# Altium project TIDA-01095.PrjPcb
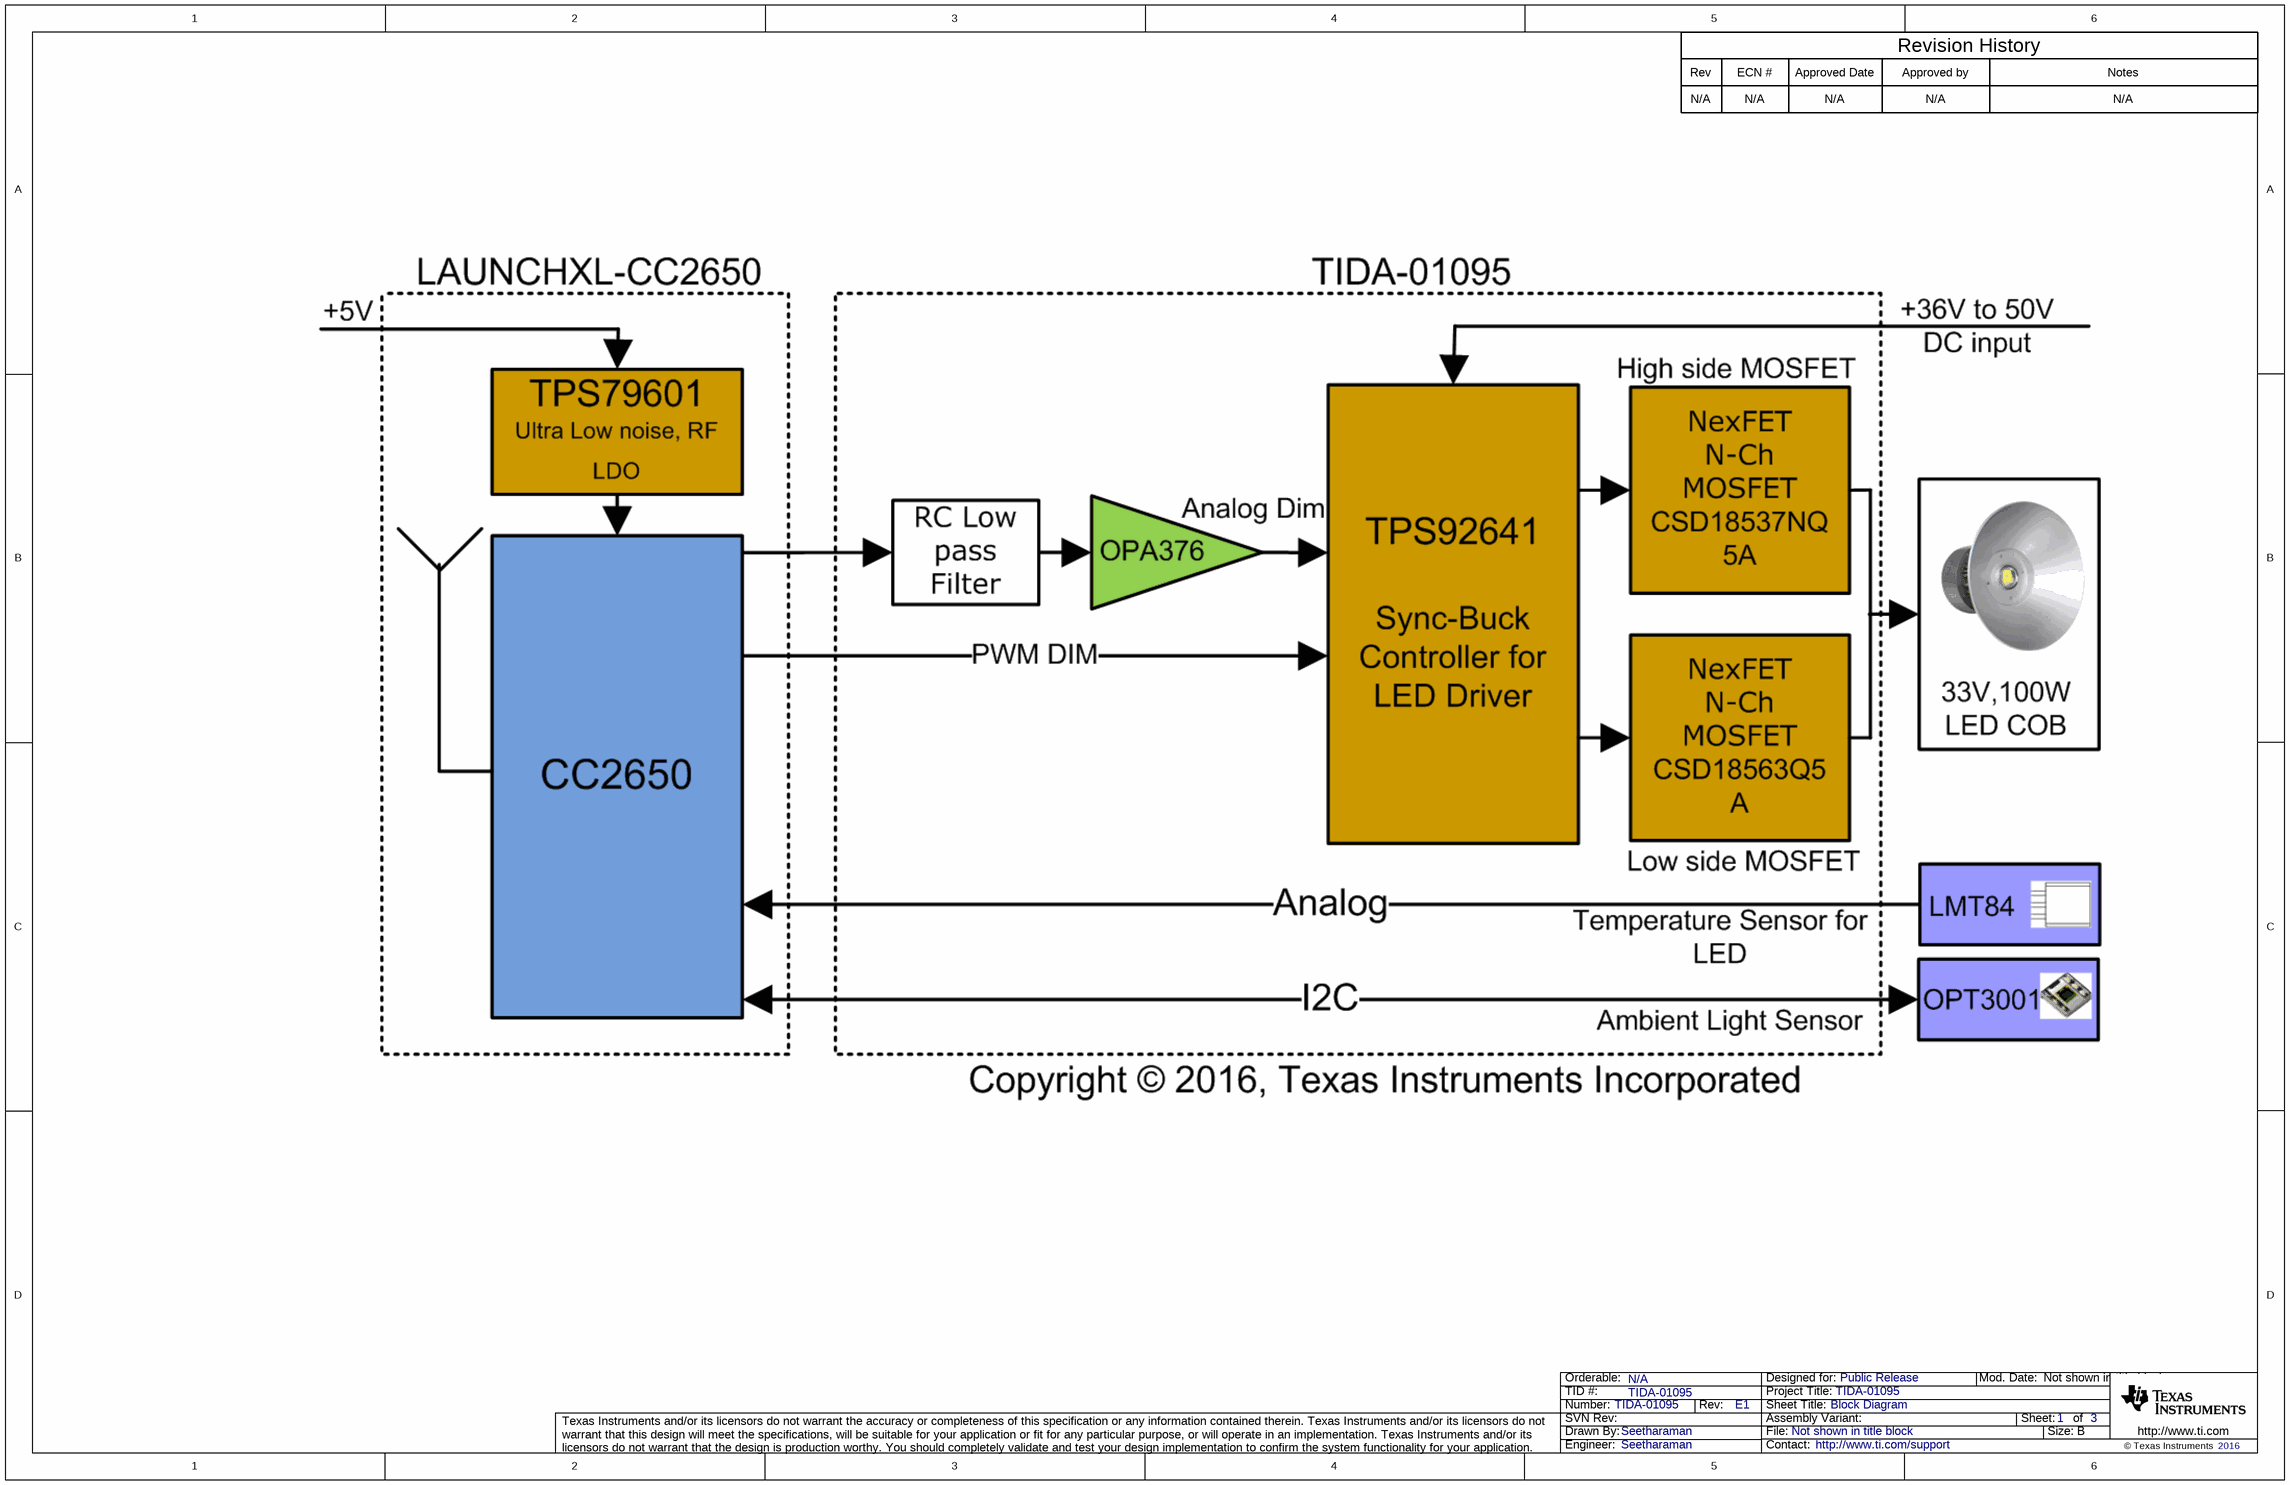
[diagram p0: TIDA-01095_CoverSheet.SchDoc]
CopyrightYear: 2016; EVM_Orderable: N/A; PCB_Layout: Avinash; PCB_Rev: E1; PRJ_Customer: Public Release; PRJ_Engineer: Seetharaman; PRJ_Number: TIDA-01095; PRJ_Title: TIDA-01095; SCH_Rev: E1; TechSupport: http://www.ti.com/support; TID: TIDA-01095
3 sheets, 80 parts. Net scope: global (net labels, ports and power ports of the same name join across sheets).
Board file: TIDA-01095.PcbDoc
Sheets:
  TIDA-01095_CoverSheet.SchDoc
  TIDA-01095_Sheet1.SchDoc
  TIDA-01095_Hardware.SchDoc

## Sheet TIDA-01095_CoverSheet.SchDoc: Block Diagram
size 431 x 279 mm; Date: Not shown in title block; ApprovedBy: Not shown in title block; CheckedBy: Not shown in title block; Author: Not shown in title block; CompanyName: Not shown in title block; DrawnBy: Seetharaman; Engineer: Not shown in title block; Organization: Not shown in title block; Address1: Not shown in title block; Address2: Not shown in title block; Address3: Not shown in title block; Address4: Not shown in title block; DocumentNumber: 1; Revision: Use project parameter SCH_Rev; SheetNumber: 1; SheetTotal: 3; PageSetup: Record=PageOptions¦CenterHorizontal=True¦CenterVertical=True¦PrintScale=1.00¦XCorrection=1.00¦YCorrection=1.00¦PrintKind=0¦BorderSize=5000000¦LeftOffset=0¦BottomOffset=0¦Orientation=2¦PaperLength=1000¦PaperWidth=1000¦Scale=100¦PaperSource=15¦PrintQuality=600¦MediaType=1¦DitherType=10¦PaperKind=Letter¦PrintScaleMode=1

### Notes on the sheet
- Rev
- N/A
- ECN #
- Approved Date
- Approved by
- Revision History
- Notes

## Sheet TIDA-01095_Sheet1.SchDoc: TIDA-01095
size 431 x 279 mm; Date: Not shown in title block; ApprovedBy: Not shown in title block; CheckedBy: Not shown in title block; Author: Not shown in title block; CompanyName: Not shown in title block; DrawnBy: Seetharaman; Engineer: Not shown in title block; Organization: Not shown in title block; Address1: Not shown in title block; Address2: Not shown in title block; Address3: Not shown in title block; Address4: Not shown in title block; DocumentNumber: 1; Revision: Use project parameter SCH_Rev; SheetNumber: 2; SheetTotal: 3; PageSetup: Record=PageOptions¦CenterHorizontal=True¦CenterVertical=True¦PrintScale=1.00¦XCorrection=1.00¦YCorrection=1.00¦PrintKind=0¦BorderSize=5000000¦LeftOffset=0¦BottomOffset=0¦Orientation=2¦PaperLength=1000¦PaperWidth=1000¦Scale=100¦PaperSource=15¦PrintQuality=600¦MediaType=1¦DitherType=10¦PaperKind=Letter¦PrintScaleMode=1
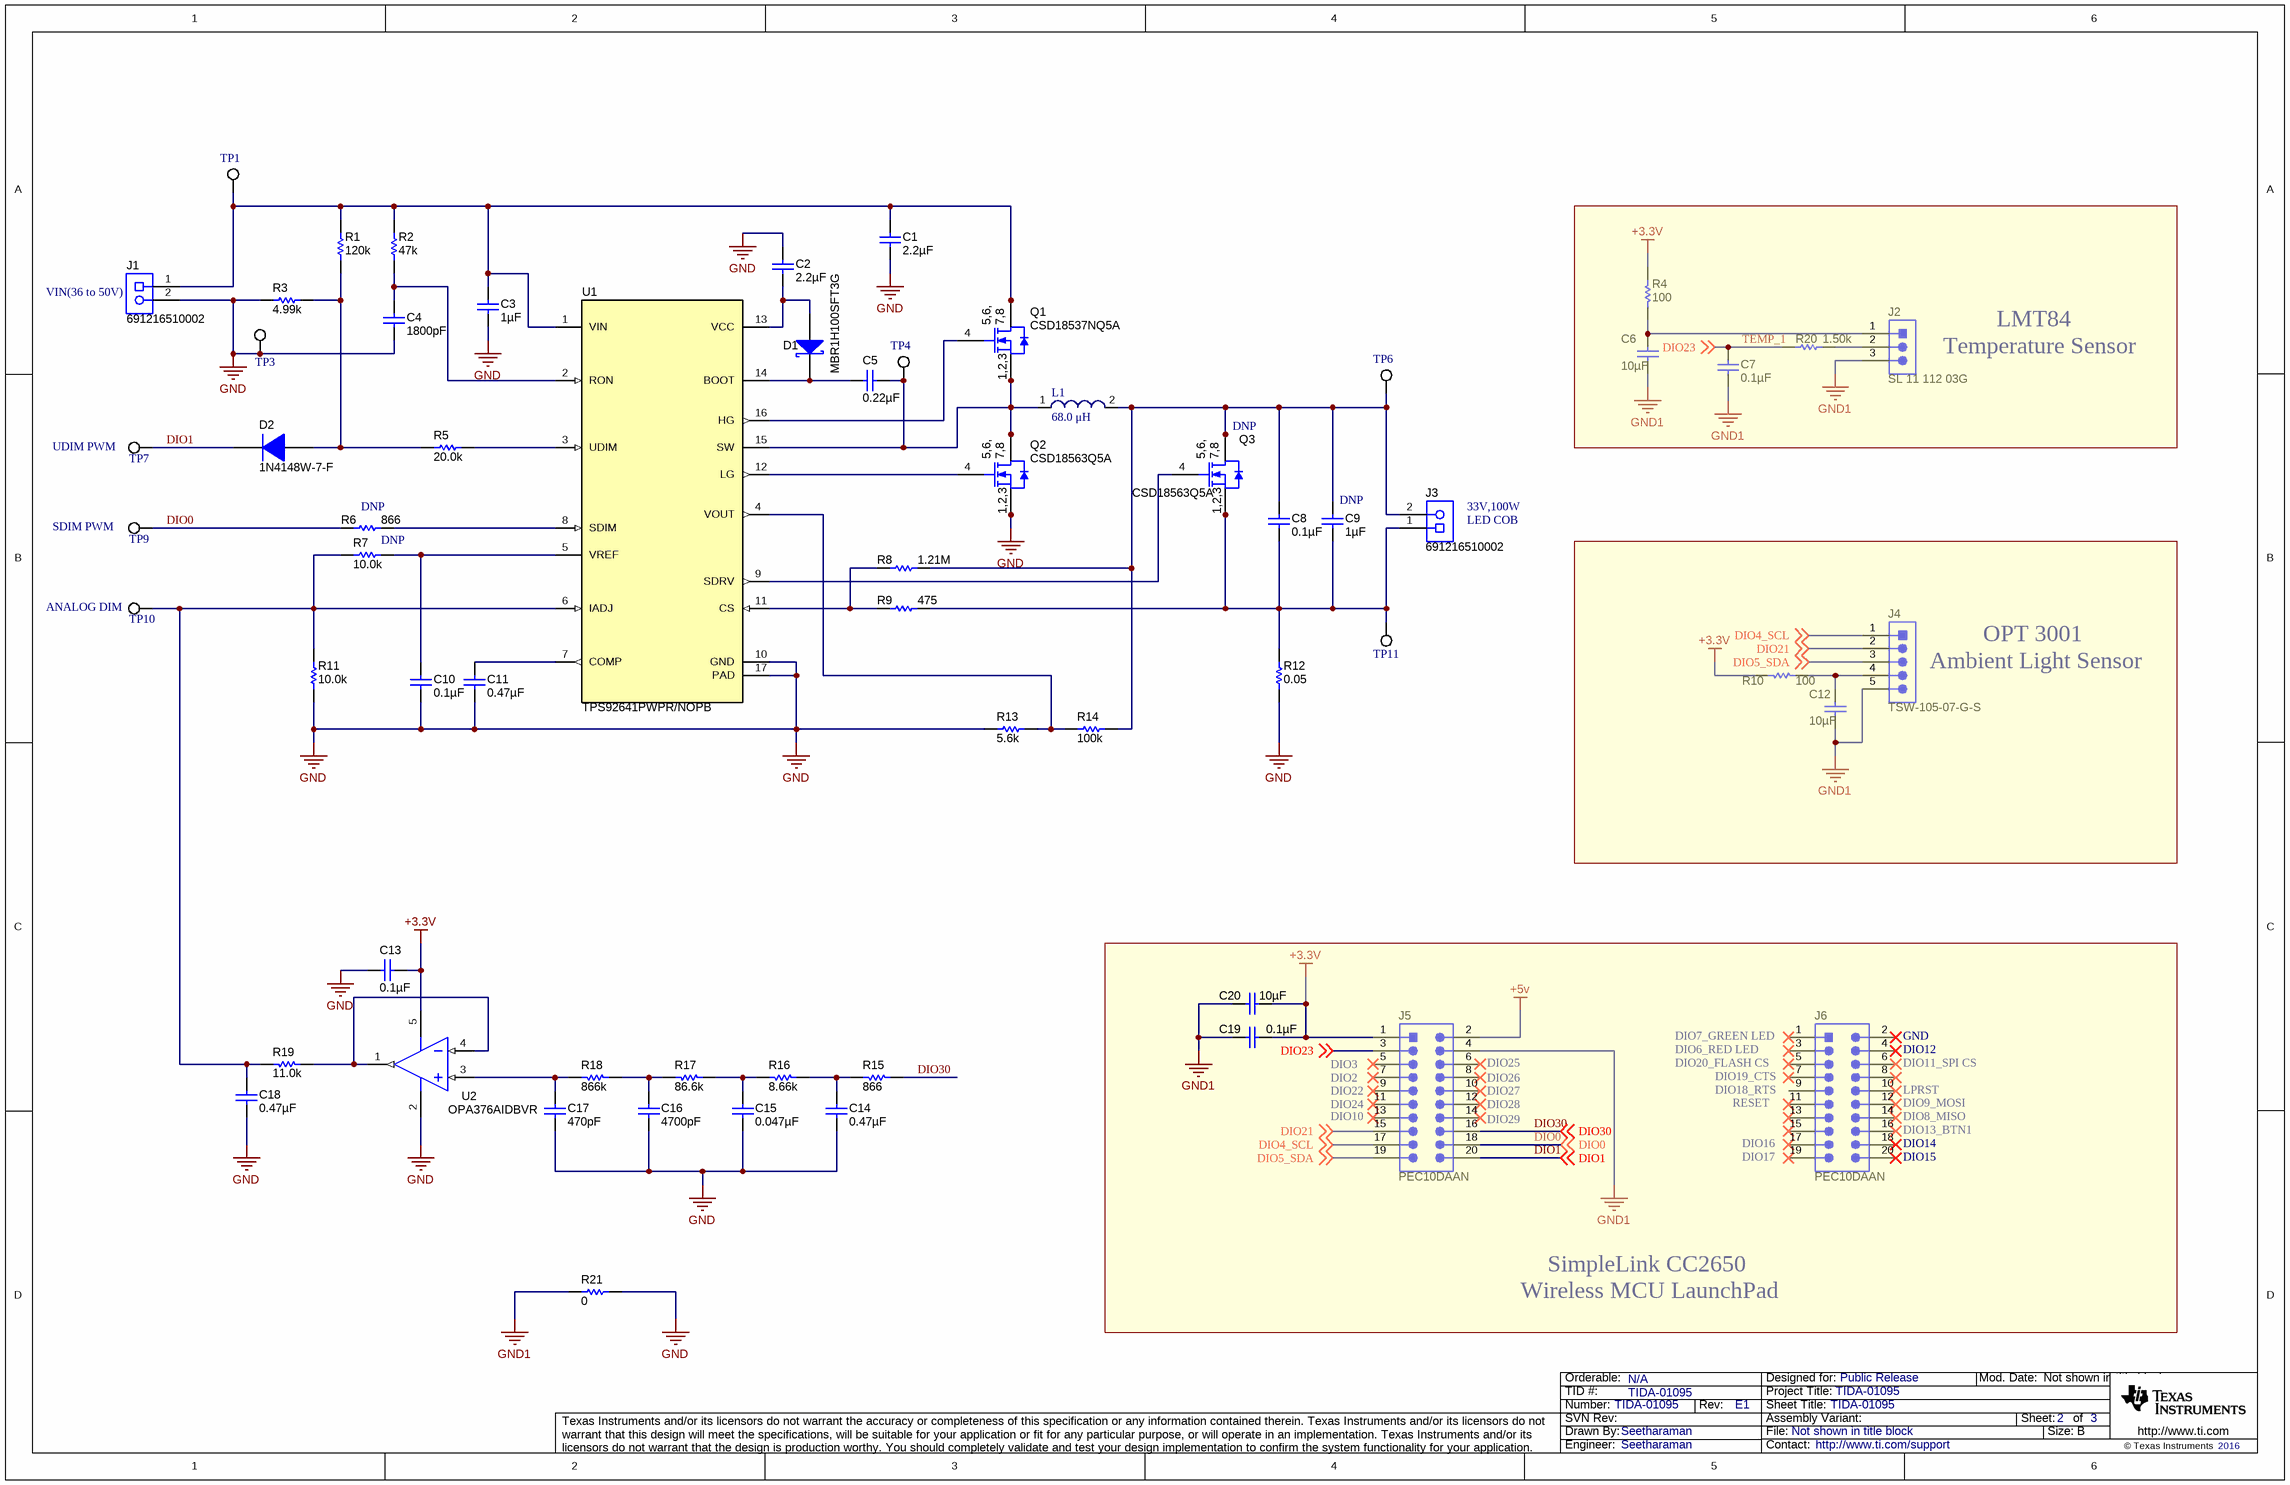
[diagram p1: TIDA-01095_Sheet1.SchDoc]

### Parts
C1  ValueDisplayed: 2.2µF  [1210_270]  (hidden comment: GRM32ER72A225KA35L)
C2  ValueDisplayed: 2.2µF  [0603]  (hidden comment: GRM188R61C225KE15D)
C3  ValueDisplayed: 1µF  [1210]  (hidden comment: C3225X7R2A105K200AA)
C4  ValueDisplayed: 1800pF  [0603]  (hidden comment: GRM188R71E182KA01D)
C5  ValueDisplayed: 0.22µF  [0603]  (hidden comment: GRM188R71E224KA88D)
C6  ValueDisplayed: 10µF  [0603]  (hidden comment: GRT188C81A106ME13D)
C7  ValueDisplayed: 0.1µF  [0603]  (hidden comment: GRM188R71E104KA01D)
C8  ValueDisplayed: 0.1µF  [0603]  (hidden comment: GRM188R71E104KA01D)
C9  ValueDisplayed: 1µF  [1210_200]  (hidden comment: GRM32RR71H105KA01L)
C10  ValueDisplayed: 0.1µF  [0603]  (hidden comment: GRM188R71E104KA01D)
C11  ValueDisplayed: 0.47µF  [0603]  (hidden comment: CGA3E3X7R1E474K080AB)
C12  ValueDisplayed: 10µF  [0603]  (hidden comment: GRT188C81A106ME13D)
C13  ValueDisplayed: 0.1µF  [0603]  (hidden comment: GRM188R71E104KA01D)
C14  ValueDisplayed: 0.47µF  [0603]  (hidden comment: GRM188R70J474KA01D)
C15  ValueDisplayed: 0.047µF  [0603]  (hidden comment: GRM188R70J473KA01D)
C16  ValueDisplayed: 4700pF  [0603]  (hidden comment: GCM188R71H472KA37D)
C17  ValueDisplayed: 470pF  [0603]  (hidden comment: C0603X471K5RACTU)
C18  ValueDisplayed: 0.47µF  [0603]  (hidden comment: GRM188R70J474KA01D)
C19  ValueDisplayed: 0.1µF  [0603]  (hidden comment: GRM188R71E104KA01D)
C20  ValueDisplayed: 10µF  [0603]  (hidden comment: GRT188C81A106ME13D)
D1  MBR1H100SFT3G  [SOD-123FL]
D2  1N4148W-7-F  [SOD-123]
J1  691216510002  [Wurth_691216510002]
J2  SL 11 112 03G  [Fischer_SL-11-112-03G]
J3  691216510002  [Wurth_691216510002]
J4  TSW-105-07-G-S  [TSW-105-07-G-S]
J5  PEC10DAAN  [SULLINS_PEC10DAAN]
J6  PEC10DAAN  [SULLINS_PEC10DAAN]
L1  68.0 μH  [WE-HCI 2212]
Q1  CSD18537NQ5A  [TRANS_NexFET_Q5A]
Q2  CSD18563Q5A  [TRANS_NexFET_Q5A]
Q3  CSD18563Q5A  [TRANS_NexFET_Q5A]
R1  ValueDisplayed: 120k  [0603]  (hidden comment: CRCW0603120KJNEA)
R2  ValueDisplayed: 47k  [0603]  (hidden comment: CRCW060347K0JNEA)
R3  ValueDisplayed: 4.99k  [0603]  (hidden comment: CRCW06034K99FKEA)
R4  ValueDisplayed: 100  [0603]  (hidden comment: RC0603FR-07100RL)
R5  ValueDisplayed: 20.0k  [0603]  (hidden comment: CRCW060320K0FKEA)
R6  ValueDisplayed: 866  [0603]  (hidden comment: RC0603FR-07866RL)
R7  ValueDisplayed: 10.0k  [0603]  (hidden comment: CRCW060310K0FKEA)
R8  ValueDisplayed: 1.21M  [0603]  (hidden comment: CRCW06031M21FKEA)
R9  ValueDisplayed: 475  [0603]  (hidden comment: CRCW0603475RFKEA)
R10  ValueDisplayed: 100  [0603]  (hidden comment: RC0603FR-07100RL)
R11  ValueDisplayed: 10.0k  [0603]  (hidden comment: CRCW060310K0FKEA)
R12  ValueDisplayed: 0.05  [2512]  (hidden comment: CSRN2512FK50L0)
R13  ValueDisplayed: 5.6k  [0603]  (hidden comment: CRCW06035K60JNEA)
R14  ValueDisplayed: 100k  [0603]  (hidden comment: RC0603FR-07100KL)
R15  ValueDisplayed: 866  [0603]  (hidden comment: RC0603FR-07866RL)
R16  ValueDisplayed: 8.66k  [0603]  (hidden comment: RC0603FR-078K66L)
R17  ValueDisplayed: 86.6k  [0603]  (hidden comment: CRCW060386K6FKEA)
R18  ValueDisplayed: 866k  [0603]  (hidden comment: RC0603FR-07866KL)
R19  ValueDisplayed: 11.0k  [0603]  (hidden comment: CRCW060311K0FKEA)
R20  ValueDisplayed: 1.50k  [0603]  (hidden comment: RC0603FR-071K5L)
R21  ValueDisplayed: 0  [1206]  (hidden comment: MCR18EZHJ000)
TP1  5002  [Keystone5002]  (value not drawn)
TP3  5002  [Keystone5002]  (value not drawn)
TP4  5002  [Keystone5002]  (value not drawn)
TP6  5002  [Keystone5002]  (value not drawn)
TP7  5002  [Keystone5002]  (value not drawn)
TP9  5002  [Keystone5002]  (value not drawn)
TP10  5002  [Keystone5002]  (value not drawn)
TP11  5002  [Keystone5002]  (value not drawn)
U1  TPS92641PWPR/NOPB  [PWP0016A_N]
U2  OPA376AIDBVR  [DBV0005A_N]

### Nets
+3.3V: C13.1 C19.1 C20.2 J5.1 R4.2 R10.1 U2.5(V+)
+5v: J5.2
GND: C1.2 C2.2 C3.2 C4.2 C10.2 C11.2 C13.2 C14.2 C15.2 C16.2 C17.2 C18.2 J1.2 Q2.1(S) Q2.2(S) Q2.3(S) R3.1 R11.1 R12.1 R13.1 R21.2 TP3.1 U1.10(GND) U1.17(PAD) U2.2(V-)
GND1: C6.2 C7.2 C12.2 C19.2 C20.1 J2.3 J4.5 J5.4 R21.1
DIO0: J5.18 R6.1 TP9.1 ; off-sheet DIO0
DIO1: D2.1(K) J5.20 TP7.1 ; off-sheet DIO1
DIO4_SCL: J4.1 J5.17 ; off-sheet DIO4_SCL
DIO5_SDA: J4.3 J5.19 ; off-sheet DIO5_SDA
DIO21: J4.2 J5.15 ; off-sheet DIO21
DIO30: J5.16 R15.1 ; off-sheet DIO30
TEMP_1: C7.1 J5.3 R20.1 ; off-sheet DIO23  [also labelled DIO23]
NetC1_1: C1.1 C3.1 J1.1 Q1.5(D) Q1.6(D) Q1.7(D) Q1.8(D) Q1.9(D) R1.2 R2.2 TP1.1 U1.1(VIN)
NetC2_1: C2.1 D1.2(A) U1.13(VCC)
NetC4_1: C4.1 R2.1 U1.2(RON)
NetC5_1: C5.1 L1.1 Q1.1(S) Q1.2(S) Q1.3(S) Q2.5(D) Q2.6(D) Q2.7(D) Q2.8(D) Q2.9(D) TP4.1 U1.15(SW)
NetC5_2: C5.2 D1.1(K) U1.14(BOOT)
NetC6_1: C6.1 J2.1 R4.1
NetC8_1: C8.1 C9.1 J3.2 L1.2 Q3.5(D) Q3.6(D) Q3.7(D) Q3.8(D) Q3.9(D) R8.2 R14.2 TP6.1
NetC8_2: C8.2 C9.2 J3.1 Q3.1(S) Q3.2(S) Q3.3(S) R9.2 R12.2 TP11.1
NetC10_1: C10.1 R7.2 U1.5(VREF)
NetC11_1: C11.1 U1.7(COMP)
NetC12_1: C12.1 J4.4 R10.2
NetC14_1: C14.1 R15.2 R16.1
NetC15_1: C15.1 R16.2 R17.1
NetC16_1: C16.1 R17.2 R18.1
NetC17_1: C17.1 R18.2 U2.3(IN+)
NetC18_1: C18.1 R7.1 R11.2 R19.2 TP10.1 U1.6(IADJ)
NetD2_2: D2.2(A) R1.1 R3.2 R5.1
NetJ2_2: J2.2 R20.2
NetQ1_4: Q1.4(G) U1.16(HG)
NetQ2_4: Q2.4(G) U1.12(LG)
NetQ3_4: Q3.4(G) U1.9(SDRV)
NetR5_2: R5.2 U1.3(UDIM)
NetR6_2: R6.2 U1.8(SDIM)
NetR8_1: R8.1 R9.1 U1.11(CS)
NetR13_2: R13.2 R14.1 U1.4(VOUT)
NetR19_1: R19.1 U2.1(OUT) U2.4(IN-)

Not connected (* = marked no-connect by the designer): J5 5* 6* 7* 8* 9* 10* 11* 12* 13* 14*; J6 1* 2* 3* 4* 5* 6* 7* 8* 9 10* 11* 12* 13* 14* 15* 16* 17* 18* 19* 20*

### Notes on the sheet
- (near J1) VIN(36 to 50V)
- Temperature Sensor
- LMT84
- (near Q3) DNP
- (near TP7) UDIM PWM
- (near TP9) SDIM PWM
- (near R6) DNP
- DNP
- (near C9) DNP
- (near J3) 33V,100W
- (near J3) LED COB
- (near TP10) ANALOG DIM
- (near J4) Ambient Light Sensor
- OPT 3001
- (near J5) DIO3
- (near J5) DIO2
- (near J5) DIO22
- (near J5) DIO25
- (near J5) DIO26
- (near J5) DIO27
- DIO7_GREEN LED
- DIO6_RED LED
- DIO20_FLASH CS
- (near J6) DIO19_CTS
- (near J6) DIO18_RTS
- (near J6) RESET
- (near J6) DIO11_SPI CS
- (near J6) LPRST
- (near J6) DIO9_MOSI
- (near J6) DIO12
- (near J6) GND
- (near J5) DIO24
- (near J5) DIO10
- (near J5) DIO28
- (near J5) DIO29
- (near J6) DIO16
- (near J6) DIO17
- (near J6) DIO8_MISO
- (near J6) DIO13_BTN1
- (near J6) DIO14
- (near J6) DIO15
- Wireless MCU LaunchPad
- SimpleLink CC2650

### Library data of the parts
C1 = GRM32ER72A225KA35L: CAP, CERM, 2.2 µF, 100 V, +/- 10%, X7R, 1210; Manufacturer: MuRata; Polarized: N; CompType: Capacitor; Value: 2.2uF; U/M: EA; Cap_F: 0.0000022; Tolerance_%: 10; ESR_ohm: 0.007; Value1: 0.007 ohm; VDC_V: 100; Value2: 100V; IRMS_A: 4.4; TaMin_C: -55; TaMax_C: 125; Cap_Case: 1210; AEC Category: Q200
C2 = GRM188R61C225KE15D: CAP, CERM, 2.2 µF, 16 V, +/- 10%, X5R, 0603; Manufacturer: MuRata; Polarized: N; CompType: Capacitor; Value: 2.2uF; U/M: EA; Cap_F: 0.0000022; Tolerance_%: 10; Value1: Unknown; VDC_V: 16; Value2: 16V; TaMin_C: -55; TaMax_C: 85; AEC Category: Q200
C3 = C3225X7R2A105K200AA: CAP, CERM, 1 µF, 100 V, +/- 10%, X7R, 1210; Manufacturer: TDK; Polarized: N; CompType: Capacitor; Value: 1uF; U/M: EA; Cap_F: 0.000001; Tolerance_%: 10; Value1: Unknown; VDC_V: 100; Value2: 100V; TaMin_C: -55; TaMax_C: 125; AEC Category: Q200
C4 = GRM188R71E182KA01D: CAP, CERM, 1800 pF, 25 V, +/- 10%, X7R, 0603; Manufacturer: MuRata; Polarized: N; CompType: Capacitor; Value: 1800pF; U/M: EA; Cap_F: 0.0000000018; Tolerance_%: 10; Value1: Unknown; VDC_V: 25; Value2: 25V; TaMin_C: -55; TaMax_C: 125; AEC Category: Q200; SizeArea_mm2: 1.28; SizeAreaWB_mm2: 4.68; SizeX_mm: 1.6; SizeY_mm: 0.8; SizeZ_mm: 1
C5 = GRM188R71E224KA88D: CAP, CERM, 0.22 µF, 25 V, +/- 10%, X7R, 0603; Manufacturer: MuRata; Polarized: N; CompType: Capacitor; Value: 0.22uF; U/M: EA; Cap_F: 0.00000022; Tolerance_%: 10; Value1: Unknown; VDC_V: 25; Value2: 25V; TaMin_C: -55; TaMax_C: 125; AEC Category: Q200
C6 C12 C20 = GRT188C81A106ME13D: CAP, CERM, 10 µF, 10 V, +/- 20%, X6S, AEC-Q200 Grade 2, 0603; Manufacturer: MuRata; Polarized: N; CompType: Capacitor; Value: 10uF; U/M: EA; Cap_F: 0.00001; Tolerance_%: 20; Value1: Unknown; VDC_V: 10; Value2: 10V; TaMin_C: -55; TaMax_C: 105; AEC Category: Q200; AEC Qualified: Y; AEC Grade: 2
C7 C8 C10 C13 C19 = GRM188R71E104KA01D: CAP, CERM, 0.1 µF, 25 V, +/- 10%, X7R, 0603; Manufacturer: MuRata; Polarized: N; CompType: Capacitor; Value: 0.1uF; U/M: EA; Cap_F: 0.0000001; Tolerance_%: 10; Value1: Unknown; VDC_V: 25; Value2: 25V; TaMin_C: -55; TaMax_C: 125; AEC Category: Q200
C9 = GRM32RR71H105KA01L: CAP, CERM, 1 µF, 50 V, +/- 10%, X7R, 1210; Manufacturer: MuRata; Polarized: N; CompType: Capacitor; Value: 1uF; U/M: EA; Cap_F: 0.000001; Tolerance_%: 10; ESR_ohm: 0.003; Value1: 0.003 ohm; VDC_V: 50; Value2: 50V; TaMin_C: -55; TaMax_C: 125; Cap_Case: 1210; AEC Category: Q200
C11 = CGA3E3X7R1E474K080AB: CAP, CERM, 0.47 µF, 25 V, +/- 10%, X7R, AEC-Q200 Grade 1, 0603; Manufacturer: TDK; Polarized: N; CompType: Capacitor; Value: 0.47uF; U/M: EA; Cap_F: 0.00000047; Tolerance_%: 10; Value1: Unknown; VDC_V: 25; Value2: 25V; TaMin_C: -55; TaMax_C: 125; AEC Category: Q200; AEC Qualified: Y; AEC Grade: 1
C14 C18 = GRM188R70J474KA01D: CAP, CERM, 0.47 µF, 6.3 V, +/- 10%, X7R, 0603; Manufacturer: MuRata; Polarized: N; CompType: Capacitor; Value: 0.47uF; U/M: EA; Cap_F: 0.00000047; Tolerance_%: 10; Value1: Unknown; VDC_V: 6.3; Value2: 6.3V; TaMin_C: -55; TaMax_C: 125; AEC Category: Q200
C15 = GRM188R70J473KA01D: CAP, CERM, 0.047 µF, 6.3 V, +/- 10%, X7R, 0603; Manufacturer: MuRata; Polarized: N; CompType: Capacitor; Value: 0.047uF; U/M: EA; Cap_F: 0.000000047; Tolerance_%: 10; Value1: Unknown; VDC_V: 6.3; Value2: 6.3V; TaMin_C: -55; TaMax_C: 125; AEC Category: Q200
C16 = GCM188R71H472KA37D: CAP, CERM, 4700 pF, 50 V, +/- 10%, X7R, AEC-Q200 Grade 1, 0603; Manufacturer: MuRata; Polarized: N; CompType: Capacitor; Value: 4700pF; U/M: EA; Cap_F: 0.0000000047; Tolerance_%: 10; Value1: Unknown; VDC_V: 50; Value2: 50V; TaMin_C: -55; TaMax_C: 125; AEC Category: Q200; AEC Qualified: Y; AEC Grade: 1
C17 = C0603X471K5RACTU: CAP, CERM, 470 pF, 50 V, +/- 10%, X7R, 0603; Manufacturer: Kemet; Polarized: N; CompType: Capacitor; Value: 470pF; U/M: EA; Cap_F: 0.00000000047; Tolerance_%: 10; Value1: Unknown; VDC_V: 50; Value2: 50V; TaMin_C: -55; TaMax_C: 125; AEC Category: Q200
D1 = MBR1H100SFT3G: Diode, Schottky, 100 V, 1 A, SOD-123FL; Manufacturer: ON Semiconductor; U/M: EA; Vf_V: 0.76; Value: 100V; Value1: 1A; Value2: 0.76V; Io_A: 1; Vr_V: 100; TJmax_C: 175; RJC_CperW: 85; SizeAreaWB_mm2: 13.44; SizeArea_mm2: 6.84; SizeX_mm: 3.8; SizeY_mm: 1.8; AEC Category: Q101
D2 = 1N4148W-7-F: Diode, Ultrafast, 100 V, 0.15 A, SOD-123; Manufacturer: Diodes Inc.; U/M: EA; Vf_V: 1.25; Value: 100V; Value1: 0.15A; Value2: 1.25V; Io_A: 0.15; Vr_V: 100; TJmax_C: 150; AEC Category: Q101
J1 J3 = 691216510002: Receptacle, 5.08mm, 2x1, Brass, TH; Manufacturer: Wurth Elektronik; SymbolCreator: a0412235; Pitch_mm: 5.08; Gender: Female; Row_Count: 1; Current_A: 10; Voltage_V: 300; Cert_UL: Y
J2 = SL 11 112 03G: Header, 2.54mm, 3x1, Gold, TH; Manufacturer: Fischer Elektronik; SymbolCreator: a0799628
J4 = TSW-105-07-G-S: Header, 100mil, 5x1, Gold, TH; Manufacturer: Samtec; SymbolCreator: a0412235; U/M: EA
J5 J6 = PEC10DAAN: Header, 100mil, 10x2, TH; Manufacturer: Sullins Connector Solutions; SymbolCreator: a0412235; U/M: EA
L1 = WE-HCI 2212, 74435586800: WE-HCI SMD Flat Wire High Current Inductor, Inductance = 68.0 μH; Manufacturer: Wurth Elektronik
Q1 = CSD18537NQ5A: MOSFET, N-CH, 60 V, 50 A, SON 5x6mm; Manufacturer: Texas Instruments; Alternate Manufacturer: None; U/M: EA; ChType: N; Value: 60V; VdsMax_V: 60; Value1: 0.036 ohm; Rdson45_ohm: 0.036; Value2: 14 nC; QgTyp_nC: 14; Vgs_V: 20; IdsMax_A: 50; AEC Category: Q101; SizeAreaWB_mm2: 55.2; SizeArea_mm2: 29.4; SizeX_mm: 6; SizeY_mm: 4.9; SizeZ_mm: 1
Q2 Q3 = CSD18563Q5A: MOSFET, N-CH, 60 V, 15 A, SON 5x6mm; Manufacturer: Texas Instruments; Alternate Manufacturer: None; U/M: EA; ChType: N; Value: 60V; VdsMax_V: 60; Value1: 0.0086 ohm; Rdson45_ohm: 0.0086; Value2: 15 nC; QgTyp_nC: 15; Vgs_V: 20; AEC Category: Q101
R1 = CRCW0603120KJNEA: RES, 120 k, 5%, 0.1 W, 0603; Manufacturer: Vishay-Dale; CompType: Resistor; Value: 120k; Res_ohm: 120000; Tolerance_%: 5; Power_W: 0.1; Value2: 0.1W; VDC_V: 75; TempCo: 200 ppm/C; EIA_Code: E24; U/M: EA; AEC Category: Q200; SizeArea_mm2: 1.28; SizeX_mm: 1.6; SizeY_mm: 0.8; SizeZ_mm: 1
R2 = CRCW060347K0JNEA: RES, 47 k, 5%, 0.1 W, 0603; Manufacturer: Vishay-Dale; CompType: Resistor; Value: 47k; Res_ohm: 47000; Value_Code: 47k0; Tolerance_%: 5; Power_W: 0.1; Value2: 0.1W; VDC_V: 75; TempCo: 200 ppm/C; EIA_Code: E24; U/M: EA; AEC Category: Q200; SizeArea_mm2: 1.28; SizeX_mm: 1.6; SizeY_mm: 0.8; SizeZ_mm: 1
R3 = CRCW06034K99FKEA: RES, 4.99 k, 1%, 0.1 W, 0603; Manufacturer: Vishay-Dale; CompType: Resistor; Value: 4.99k; Res_ohm: 4990; Value_Code: 4k99; Tolerance_%: 1; Power_W: 0.1; Value2: 0.1W; VDC_V: 75; TempCo: 100 ppm/C; EIA_Code: E96; U/M: EA; AEC Category: Q200; SizeArea_mm2: 1.28; SizeX_mm: 1.6; SizeY_mm: 0.8
R4 R10 = RC0603FR-07100RL: RES, 100, 1%, 0.1 W, 0603; Manufacturer: Yageo America; CompType: Resistor; Value: 100; Value_Code: 100R; Tolerance_%: 1; Power_W: 0.1; Value2: 0.1W; VDC_V: 150; TempCo: 200 ppm/C; EIA_Code: E96; U/M: EA; AEC Category: Q200
R5 = CRCW060320K0FKEA: RES, 20.0 k, 1%, 0.1 W, 0603; Manufacturer: Vishay-Dale; CompType: Resistor; Value: 20.0k; Res_ohm: 20000; Value_Code: 20k0; Tolerance_%: 1; Power_W: 0.1; Value2: 0.1W; VDC_V: 75; TempCo: 100 ppm/C; EIA_Code: E96; U/M: EA; AEC Category: Q200
R6 R15 = RC0603FR-07866RL: RES, 866, 1%, 0.1 W, 0603; Manufacturer: Yageo America; CompType: Resistor; Value: 866; Value_Code: 866R; Tolerance_%: 1; Power_W: 0.1; Value2: 0.1W; VDC_V: 150; TempCo: 200 ppm/C; EIA_Code: E96; U/M: EA; AEC Category: Q200
R7 R11 = CRCW060310K0FKEA: RES, 10.0 k, 1%, 0.1 W, 0603; Manufacturer: Vishay-Dale; CompType: Resistor; Value: 10.0k; Res_ohm: 10000; Value_Code: 10k0; Tolerance_%: 1; Power_W: 0.1; Value2: 0.1W; VDC_V: 75; TempCo: 100 ppm/C; EIA_Code: E96; U/M: EA; AEC Category: Q200
R8 = CRCW06031M21FKEA: RES, 1.21 M, 1%, 0.1 W, 0603; Manufacturer: Vishay-Dale; CompType: Resistor; Value: 1.21Meg; Res_ohm: 1210000; Value_Code: 1M21; Tolerance_%: 1; Power_W: 0.1; Value2: 0.1W; VDC_V: 75; TempCo: 100 ppm/C; EIA_Code: E96; U/M: EA; AEC Category: Q200
R9 = CRCW0603475RFKEA: RES, 475, 1%, 0.1 W, 0603; Manufacturer: Vishay-Dale; CompType: Resistor; Value: 475; Value_Code: 475R; Tolerance_%: 1; Power_W: 0.1; Value2: 0.1W; VDC_V: 75; TempCo: 100 ppm/C; EIA_Code: E96; U/M: EA; AEC Category: Q200
R12 = CSRN2512FK50L0: RES, 0.05, 1%, 2 W, 2512; Manufacturer: Stackpole Electronics Inc; CompType: Resistor; Value: 0.05; Value_Code: R050; Tolerance_%: 1; Power_W: 2; Value2: 2W; TempCo: 200 ppm/C; EIA_Code: E96; U/M: EA; AEC Category: Q200
R13 = CRCW06035K60JNEA: RES, 5.6 k, 5%, 0.1 W, 0603; Manufacturer: Vishay-Dale; CompType: Resistor; Value: 5.6k; Res_ohm: 5600; Value_Code: 5k60; Tolerance_%: 5; Power_W: 0.1; Value2: 0.1W; VDC_V: 75; TempCo: 200 ppm/C; EIA_Code: E24; U/M: EA; AEC Category: Q200; SizeArea_mm2: 1.28; SizeX_mm: 1.6; SizeY_mm: 0.8; SizeZ_mm: 1
R14 = RC0603FR-07100KL: RES, 100 k, 1%, 0.1 W, 0603; Manufacturer: Yageo America; CompType: Resistor; Value: 100k; Res_ohm: 100000; Tolerance_%: 1; Power_W: 0.1; Value2: 0.1W; VDC_V: 150; TempCo: 200 ppm/C; EIA_Code: E96; U/M: EA; AEC Category: Q200
R16 = RC0603FR-078K66L: RES, 8.66 k, 1%, 0.1 W, 0603; Manufacturer: Yageo America; CompType: Resistor; Value: 8.66k; Res_ohm: 8660; Value_Code: 8k66; Tolerance_%: 1; Power_W: 0.1; Value2: 0.1W; VDC_V: 150; TempCo: 200 ppm/C; EIA_Code: E96; U/M: EA; AEC Category: Q200
R17 = CRCW060386K6FKEA: RES, 86.6 k, 1%, 0.1 W, 0603; Manufacturer: Vishay-Dale; CompType: Resistor; Value: 86.6k; Res_ohm: 86600; Value_Code: 86k6; Tolerance_%: 1; Power_W: 0.1; Value2: 0.1W; VDC_V: 75; TempCo: 100 ppm/C; EIA_Code: E96; U/M: EA; AEC Category: Q200
R18 = RC0603FR-07866KL: RES, 866 k, 1%, 0.1 W, 0603; Manufacturer: Yageo America; CompType: Resistor; Value: 866k; Res_ohm: 866000; Tolerance_%: 1; Power_W: 0.1; Value2: 0.1W; VDC_V: 150; TempCo: 200 ppm/C; EIA_Code: E96; U/M: EA; AEC Category: Q200
R19 = CRCW060311K0FKEA: RES, 11.0 k, 1%, 0.1 W, 0603; Manufacturer: Vishay-Dale; CompType: Resistor; Value: 11.0k; Res_ohm: 11000; Value_Code: 11k0; Tolerance_%: 1; Power_W: 0.1; Value2: 0.1W; VDC_V: 75; TempCo: 100 ppm/C; EIA_Code: E96; U/M: EA; AEC Category: Q200; SizeArea_mm2: 1.28; SizeX_mm: 1.6; SizeY_mm: 0.8
R20 = RC0603FR-071K5L: RES, 1.50 k, 1%, 0.1 W, 0603; Manufacturer: Yageo America; CompType: Resistor; Value: 1.50k; Res_ohm: 1500; Value_Code: 1k50; Tolerance_%: 1; Power_W: 0.1; Value2: 0.1W; VDC_V: 150; TempCo: 200 ppm/C; EIA_Code: E96; U/M: EA; AEC Category: Q200
R21 = MCR18EZHJ000: RES, 0, 5%, 0.25 W, 1206; Manufacturer: Rohm; CompType: Resistor; Value: 0; Value_Code: 0000; Tolerance_%: 5; Power_W: 0.25; Value2: 0.25W; VDC_V: 200; TempCo: 200 ppm/C; EIA_Code: E24; U/M: EA; AEC Category: Q200
TP1 TP3 TP4 TP6 TP7 TP9-TP11 = 5002: Test Point, Miniature, White, TH; Manufacturer: Keystone; CompType: Test Point Loop; U/M: EA
U1 = TPS92641PWPR/NOPB: Synchronous Buck Controller for Precision Dimming LED Drivers, PWP0016A; Alternate PartNumber: TPS92641PWP/NOPB; Manufacturer: Texas Instruments; SymbolCreator: a0411947; SizeX_mm: 6.4; SizeY_mm: 5; SizeZ_mm: 1.2; CompType: IC; U/M: EA
U2 = OPA376AIDBVR: Precision, Low Noise, Low Iq Operational Amplifier, 2.2 to 5.5 V, -40 to 125 degC, 5-pin SOT23 (DBV0005A), Green (RoHS & no Sb/Br); Manufacturer: Texas Instruments; Alternate PartNumber: Equivalent; CMRR(Min)(dB): 76; IIB(Max)(pA): 10; Iq per channel(Max)(mA): 0.95; Number of Channels: 1; Offset Drift(Typ)(uV/C): 0.32; Slew Rate(Typ)(V/us): 2; Sub Family: Low Input Bias Current Amp (<=10pA), Low Noise Amp (<=10nV/rtHz), Low Offset Voltage Amplifier (<=500uV), Low Supply Voltage Amplifier (<=2.7V), Precision Amplifier; Total Supply Voltage(Max)(+5V is 5, +/-5V is 10): 5.5; Total Supply Voltage(Min)(+5V is 5, +/-5V is 10): 2.2; Vio (25C)(Max)(mV): 0.025; Vn at 1kHz(Typ)(nV/rtHz): 7.5

## Sheet TIDA-01095_Hardware.SchDoc: Hardware
size 431 x 279 mm; Date: Not shown in title block; ApprovedBy: Not shown in title block; CheckedBy: Not shown in title block; Author: Not shown in title block; CompanyName: Not shown in title block; DrawnBy: Seetharaman; Engineer: Not shown in title block; Organization: Not shown in title block; Address1: Not shown in title block; Address2: Not shown in title block; Address3: Not shown in title block; Address4: Not shown in title block; DocumentNumber: 1; Revision: Use project parameter SCH_Rev; SheetNumber: 3; SheetTotal: 3; PageSetup: Record=PageOptions¦CenterHorizontal=True¦CenterVertical=True¦PrintScale=1.00¦XCorrection=1.00¦YCorrection=1.00¦PrintKind=0¦BorderSize=5000000¦LeftOffset=0¦BottomOffset=0¦Orientation=2¦PaperLength=1000¦PaperWidth=1000¦Scale=100¦PaperSource=15¦PrintQuality=600¦MediaType=1¦DitherType=10¦PaperKind=Letter¦PrintScaleMode=1
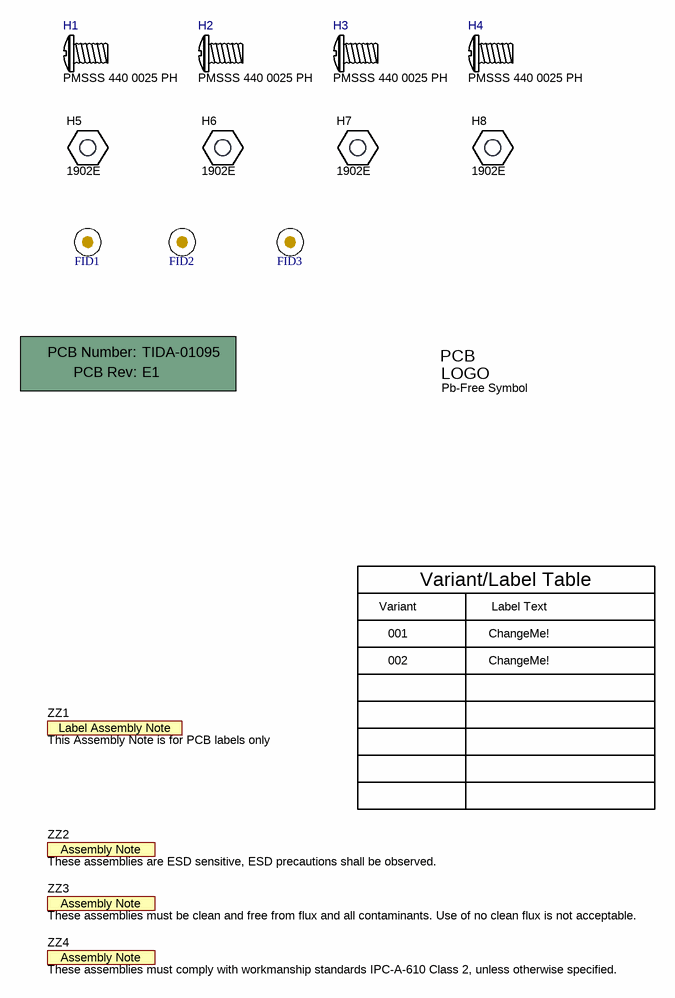
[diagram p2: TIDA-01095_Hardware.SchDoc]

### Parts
!PCB1  Printed Circuit Board  (value not drawn)  (mechanical)
FID1  Fiducial  [Fiducial10-30]  (value not drawn)
FID2  Fiducial  [Fiducial10-30]  (value not drawn)
FID3  Fiducial  [Fiducial10-30]  (value not drawn)
H1  PMSSS 440 0025 PH  [B_F_PMSSS4400025PH]
H2  PMSSS 440 0025 PH  [B_F_PMSSS4400025PH]
H3  PMSSS 440 0025 PH  [B_F_PMSSS4400025PH]
H4  PMSSS 440 0025 PH  [B_F_PMSSS4400025PH]
H5  1902E  [Keystone_1902E]
H6  1902E  [Keystone_1902E]
H7  1902E  [Keystone_1902E]
H8  1902E  [Keystone_1902E]
Logo1  Pb-Free Symbol  [Pb-Free_Overlay_Small]  (no BOM)
ZZ1  This Assembly Note is for PCB labels only  [AssemblyNoteLabel]  (no BOM)
ZZ2  These assemblies are ESD sensitive, ESD precautions shall be observed.  [AssemblyNote]  (no BOM)
ZZ3  These assemblies must be clean and free from flux and all contaminants. Use of no clean flux is not acceptable.  [AssemblyNote]  (no BOM)
ZZ4  These assemblies must comply with workmanship standards IPC-A-610 Class 2, unless otherwise specified.  [AssemblyNote]  (no BOM)

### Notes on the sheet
- Variant
- Variant/Label Table
- Label Text
- 001
- 002
- ChangeMe!

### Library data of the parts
!PCB1 = PCB: Manufacturer: Any; PartNumber: TIDA-01095; SymbolCreator: a0412235
FID1-FID3 = Fiducial: Fiducial mark.  There is nothing to buy or mount.; SymbolCreator: codlsc
H1-H4 = PMSSS 440 0025 PH: MACHINE SCREW PAN PHILLIPS 4-40; Manufacturer: B&F Fastener Supply; CompType: Standoff; SymbolCreator: a0412235
H5-H8 = 1902E: Standoff, Hex, 1"L #4-40 Nylon; Manufacturer: Keystone; CompType: Hardware; SymbolCreator: a0412235
Logo1 = Pb-Free: SymbolCreator: a0412235
ZZ1 = AssemblyNoteLabel: SymbolCreator: a0412235
ZZ2-ZZ4 = AssemblyNote: SymbolCreator: codlsc

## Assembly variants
001: not fitted C9 FID1 FID2 FID3 Q3 R6 R7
